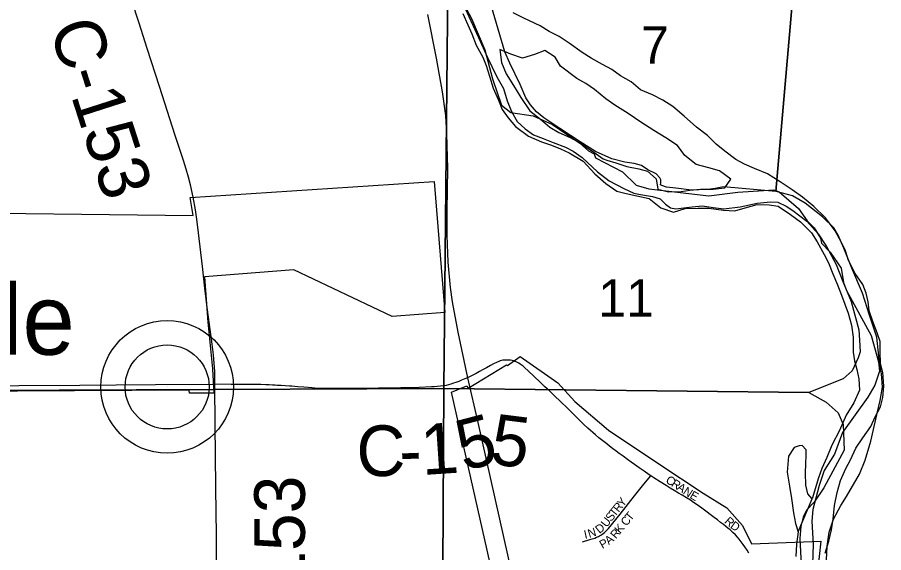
# Model space of a CAD drawing. Extents: x 0 to 680, y 0 to 440.
# Drawn here: x 499.3 to 516.42, y 256.23 to 266.81 of the extents above; entities that cross this region are included whole.
import ezdxf

# ---------------------------------------------------------------- set-up
doc = ezdxf.new("R2010")
doc.units = 0
for name, color, linetype in [('GM_X_City_Street', 7, 'Continuous'), ('GM_X_City_Street_Text', 7, 'Continuous'), ('GM_X_Corporation', 7, 'Continuous'), ('GM_X_County_Road', 7, 'Continuous'), ('GM_X_County_Road_Text', 7, 'Continuous'), ('GM_X_Major_River', 7, 'Continuous'), ('GM_X_Rail_Line', 7, 'Continuous'), ('GM_X_Section', 7, 'Continuous'), ('GM_X_Section_Text', 7, 'Continuous'), ('GM_X_Township', 7, 'Continuous'), ('GM_X_Township_Road', 7, 'Continuous'), ('GM_X_Unincorporated', 7, 'Continuous'), ('GM_X_Unincorporated_Location', 7, 'Continuous'), ('GM_X_Unincorporated_Text', 7, 'Continuous')]:
    doc.layers.add(name, color=color, linetype=linetype)

msp = doc.modelspace()

# ---------------------------------------------------------------- linework, layer by layer
at = {"layer": 'GM_X_City_Street'}
for points in [[(502.954, 261.886), (502.879, 262.549), (502.844, 262.821), (502.818, 263.005)], [(511.818, 257.749), (511.785, 257.77), (511.685, 257.837), (511.588, 257.905), (511.498, 257.969), (511.429, 258.019), (511.356, 258.073), (511.27, 258.135), (511.196, 258.189), (511.136, 258.232), (511.061, 258.289), (511.003, 258.334), (510.948, 258.377), (510.871, 258.437), (510.794, 258.499), (510.723, 258.558), (510.671, 258.603), (510.626, 258.642), (510.576, 258.689), (510.497, 258.764), (510.17, 259.084), (510.035, 259.213), (509.915, 259.328), (509.814, 259.426), (509.719, 259.516), (509.632, 259.597)], [(510.468, 256.444), (510.611, 256.487), (510.663, 256.502), (510.71, 256.518), (510.747, 256.532), (510.782, 256.548), (510.805, 256.561), (510.831, 256.576), (510.854, 256.591), (510.878, 256.608), (510.901, 256.627), (510.929, 256.652), (510.954, 256.678), (510.983, 256.709), (511.212, 256.99), (511.498, 257.353), (511.684, 257.583), (511.818, 257.749)], [(513.491, 256.58), (513.441, 256.629), (513.386, 256.678), (513.343, 256.714), (513.301, 256.747), (513.254, 256.784), (513.199, 256.827), (513.138, 256.875), (513.073, 256.926), (512.996, 256.982), (512.934, 257.03), (512.854, 257.089), (512.754, 257.16), (512.666, 257.223), (512.601, 257.265), (512.523, 257.312), (512.44, 257.363), (512.368, 257.406), (512.282, 257.457), (512.201, 257.506), (512.124, 257.553), (512.007, 257.627), (511.881, 257.708), (511.818, 257.749)], [(513.759, 256.217), (513.722, 256.28), (513.679, 256.343), (513.646, 256.393), (513.607, 256.445), (513.568, 256.493), (513.53, 256.536), (513.491, 256.58)]]:
    msp.add_lwpolyline(points, dxfattribs=at)
at = {"layer": 'GM_X_Corporation'}
for points in [[(497.251, 262.955), (502.772, 262.895), (502.714, 263.247), (507.536, 263.566), (507.745, 260.976), (506.707, 260.893), (504.759, 261.818), (502.993, 261.678), (503.065, 260.781), (503.151, 259.862), (503.178, 259.379), (502.698, 259.381), (502.694, 259.441), (498.159, 259.415)], [(509.824, 250.791), (507.877, 259.404), (508.185, 259.528), (508.21, 259.477), (508.965, 259.943), (508.986, 259.927), (509.235, 260.107), (509.983, 259.583), (510.317, 259.215), (510.982, 258.647), (511.979, 257.987), (512.857, 257.402), (513.32, 257.112), (513.634, 256.765), (513.808, 256.401), (515.179, 256.455), (515.114, 255.848)]]:
    msp.add_lwpolyline(points, dxfattribs=at)
at = {"layer": 'GM_X_County_Road'}
for points in [[(502.72, 263.496), (502.681, 263.647), (502.634, 263.811), (502.579, 263.982), (502.419, 264.471), (502.108, 265.44), (501.864, 266.19), (501.705, 266.691), (501.555, 267.16)], [(502.818, 263.005), (502.772, 263.255), (502.72, 263.496)], [(503.2, 259.686), (503.197, 259.817), (503.187, 259.967), (503.171, 260.14), (503.147, 260.348), (503.116, 260.592), (503.051, 261.073), (503.002, 261.457), (502.954, 261.886)], [(509.632, 259.597), (509.393, 259.822), (509.328, 259.883), (509.293, 259.912), (509.258, 259.938), (509.236, 259.954), (509.21, 259.972), (509.184, 259.986), (509.158, 259.998), (509.132, 260.009), (509.106, 260.018), (509.076, 260.025), (509.048, 260.03), (509.015, 260.033), (508.984, 260.034), (508.957, 260.034), (508.923, 260.033), (508.894, 260.03), (508.868, 260.025), (508.844, 260.02), (508.813, 260.009), (508.767, 259.989), (508.712, 259.962), (508.647, 259.925), (508.574, 259.883), (508.508, 259.847), (508.435, 259.808), (508.369, 259.772), (508.311, 259.741), (508.248, 259.711), (508.193, 259.686), (508.143, 259.665), (508.074, 259.636), (508.021, 259.614), (507.963, 259.592), (507.921, 259.576), (507.867, 259.557), (507.818, 259.543), (507.773, 259.533), (507.72, 259.524), (507.662, 259.517), (507.596, 259.511), (507.534, 259.507), (507.482, 259.504), (507.241, 259.495), (506.875, 259.485), (505.991, 259.476), (505.336, 259.473), (505.249, 259.476), (505.178, 259.481), (505.118, 259.485), (505.047, 259.491), (504.958, 259.498), (504.842, 259.507), (504.722, 259.517), (504.674, 259.521), (504.59, 259.527), (504.511, 259.531), (504.435, 259.535), (504.391, 259.537), (504.34, 259.54), (504.273, 259.543), (504.208, 259.547), (504.112, 259.549), (503.968, 259.551), (503.761, 259.552), (503.521, 259.554), (503.203, 259.558)], [(503.203, 259.558), (503.2, 259.686)], [(503.244, 254.088), (503.236, 255.241), (503.234, 256.578), (503.218, 257.499), (503.213, 258.176), (503.21, 258.735), (503.203, 259.558)]]:
    msp.add_lwpolyline(points, dxfattribs=at)
at = {"layer": 'GM_X_Major_River'}
msp.add_line((514.732, 256.638), (515.007, 257.29), dxfattribs=at)
for points in [[(508.102, 266.885), (508.199, 266.663), (508.284, 266.481), (508.368, 266.26), (508.499, 266.024), (508.564, 265.856), (508.629, 265.648), (508.706, 265.406), (508.81, 265.171), (508.881, 264.989), (509, 264.821), (509.145, 264.652), (509.403, 264.461), (509.656, 264.351), (509.856, 264.282), (510.035, 264.212), (510.208, 264.13), (510.48, 263.966), (510.711, 263.716), (510.929, 263.526), (511.148, 263.376), (511.335, 263.327), (511.541, 263.278), (511.788, 263.228), (512.02, 263.044), (512.266, 262.961), (512.501, 263.032), (512.748, 263.035), (512.969, 263.039), (513.256, 262.996), (513.483, 262.986), (513.684, 263.044), (513.919, 263.108), (514.159, 263.105), (514.339, 263.076), (514.578, 262.913), (514.777, 262.77), (514.995, 262.553), (515.106, 262.371), (515.244, 262.122), (515.335, 261.954), (515.42, 261.739), (515.511, 261.524), (515.589, 261.315), (515.653, 261.141), (515.718, 260.959), (515.789, 260.725), (515.819, 260.49), (515.823, 260.189), (515.847, 260.022), (515.892, 259.847), (515.93, 259.666), (515.948, 259.439), (515.831, 259.193), (515.681, 258.947), (515.55, 258.641), (515.4, 258.355), (515.297, 258.109), (515.201, 257.89), (515.132, 257.71), (515.007, 257.29)], [(514.816, 263.257), (514.611, 263.4), (514.378, 263.557), (514.126, 263.714), (513.867, 263.824), (513.674, 263.907), (513.501, 263.996), (513.283, 264.166), (513.111, 264.301), (512.939, 264.471), (512.72, 264.641), (512.482, 264.858), (512.257, 265.048), (512.058, 265.17), (511.852, 265.28), (511.613, 265.376), (511.428, 265.533), (511.222, 265.655), (511.049, 265.778), (510.863, 265.874), (510.638, 266.004), (510.459, 266.113), (510.207, 266.297), (510.008, 266.433), (509.808, 266.529), (509.629, 266.638), (509.31, 266.789), (509.098, 266.899)], [(510.034, 265.844), (509.929, 266.019), (509.724, 266.156), (509.522, 266.071), (509.281, 266.001), (509.055, 266.084), (508.835, 266.173), (508.866, 265.919), (508.957, 265.69), (509.108, 265.461), (509.252, 265.225), (509.429, 264.962), (509.641, 264.793), (509.82, 264.636), (509.999, 264.534), (510.225, 264.437), (510.418, 264.328), (510.65, 264.178), (510.875, 264.015)], [(510.875, 264.015), (510.948, 263.987), (511.128, 263.931), (511.348, 263.862), (511.581, 263.812), (511.754, 263.77), (511.926, 263.614), (511.957, 263.413), (512.171, 263.363), (512.418, 263.367), (512.592, 263.392), (512.8, 263.416), (513.053, 263.413), (513.281, 263.437), (513.403, 263.609), (513.178, 263.772), (512.965, 263.835), (512.718, 263.898), (512.493, 264.075), (512.348, 264.277), (512.116, 264.427), (511.877, 264.571), (511.619, 264.734), (511.373, 264.911), (511.108, 265.075), (510.929, 265.198), (510.704, 265.381), (510.532, 265.504), (510.359, 265.599), (510.034, 265.844)], [(515.268, 256.217), (515.338, 256.457), (515.394, 256.677), (515.423, 256.891), (515.453, 257.158), (515.503, 257.418), (515.572, 257.658), (515.675, 257.891), (515.764, 258.063), (515.874, 258.296), (516.01, 258.495), (516.166, 258.721), (516.255, 258.913), (516.358, 259.113), (516.407, 259.293), (516.423, 259.52), (516.406, 259.788), (516.361, 259.975), (516.351, 260.196), (516.353, 260.403), (516.295, 260.571), (516.211, 260.8), (516.133, 261.008), (516.115, 261.189), (516.077, 261.356), (516.012, 261.531), (515.861, 261.747), (515.73, 262.003), (515.666, 262.191), (515.587, 262.359), (515.463, 262.588), (515.272, 262.844), (515.041, 263.067), (514.816, 263.257)], [(515.007, 257.29), (514.921, 257.392), (514.883, 257.566), (514.879, 257.8), (514.881, 257.994), (514.89, 258.148), (514.891, 258.261), (514.812, 258.349), (514.752, 258.343), (514.651, 258.304), (514.542, 258.139), (514.512, 257.818), (514.562, 257.543), (514.599, 257.302), (514.642, 257.014), (514.68, 256.806), (514.732, 256.638)], [(514.732, 256.638), (514.702, 256.398), (514.686, 256.151)]]:
    msp.add_lwpolyline(points, dxfattribs=at)
at = {"layer": 'GM_X_Rail_Line'}
msp.add_lwpolyline([(509.833, 252.424), (508.403, 258.802), (508.204, 259.684), (508.01, 260.587), (507.897, 261.189), (507.862, 261.469), (507.813, 261.97), (507.796, 262.499), (507.796, 262.991), (507.804, 263.821), (507.787, 264.503), (507.764, 264.868), (507.703, 265.339), (507.582, 265.999), (507.408, 266.867)], dxfattribs=at)
at = {"layer": 'GM_X_Section'}
for points in [[(514.746, 268.599), (514.294, 263.368), (513.255, 263.461), (513.094, 263.424), (512.953, 263.406), (512.766, 263.397), (512.626, 263.392), (512.313, 263.432), (512.127, 263.449), (512.04, 263.484), (512.014, 263.497), (512.015, 263.537), (512.016, 263.597), (511.997, 263.638), (511.925, 263.713), (511.759, 263.796), (511.634, 263.878), (511.488, 263.921), (511.308, 263.944), (511.049, 264.009), (510.725, 264.156), (510.421, 264.348), (510.019, 264.609), (509.703, 264.822), (509.558, 264.938), (509.441, 265.081), (509.35, 265.216), (509.234, 265.478), (509.035, 265.903), (508.933, 266.125), (508.638, 267.138)], [(515.293, 256.087), (515.304, 256.354), (515.343, 256.633), (515.434, 256.892), (515.573, 257.163), (515.69, 257.341), (515.945, 257.777), (516.057, 258.055), (516.171, 258.434), (516.222, 258.66), (516.302, 259.012), (516.353, 259.238), (516.398, 259.497), (516.383, 259.764), (516.34, 259.999), (516.329, 260.113), (516.289, 260.487), (516.144, 260.924), (516.006, 261.36), (515.794, 261.851), (515.635, 262.248), (515.526, 262.504), (515.436, 262.646), (515.213, 262.863), (514.871, 263.137), (514.62, 263.282), (514.42, 263.332), (514.294, 263.368), (514.746, 268.599)], [(507.809, 267.427), (507.727, 259.473), (489.476, 259.394)], [(508.148, 266.981), (508.411, 266.408), (508.59, 266.018), (508.777, 265.634), (508.906, 265.405), (508.981, 265.156), (509.064, 264.948), (509.174, 264.752), (509.338, 264.602), (509.503, 264.486), (509.688, 264.415), (509.887, 264.332), (510.132, 264.24), (510.284, 264.164), (510.462, 264.04), (510.764, 263.754), (510.994, 263.577), (511.285, 263.424), (511.484, 263.334), (511.617, 263.305), (511.856, 263.267), (512.002, 263.224), (512.107, 263.115), (512.206, 263.047), (512.312, 263.025), (512.473, 263.042), (512.64, 263.065), (512.841, 263.081), (513.054, 263.051), (513.26, 263.027), (513.588, 263.061), (513.923, 263.135), (514.184, 263.163), (514.33, 263.154), (514.496, 263.077), (514.628, 262.988), (514.904, 262.782), (515.126, 262.531), (515.295, 262.281), (515.482, 261.924), (515.616, 261.588), (515.782, 261.191), (515.932, 260.634), (515.948, 260.427), (515.957, 260.2), (515.921, 260.08), (515.803, 259.822), (515.62, 259.665), (514.941, 259.391), (507.727, 259.473), (507.809, 267.427)], [(507.628, 241.733), (507.727, 259.473), (514.941, 259.391), (515.284, 259.204), (515.521, 258.993), (515.623, 258.764), (515.64, 258.257), (515.239, 257.51), (515.047, 257.226), (514.897, 257.069), (514.834, 256.93), (514.784, 256.744), (514.767, 256.511), (514.801, 255.856)]]:
    msp.add_lwpolyline(points, dxfattribs=at)
msp.add_lwpolyline([(507.727, 259.473), (507.628, 241.733), (499.118, 242.119), (489.987, 242.13), (489.813, 253.134), (489.476, 259.394)], close=True, dxfattribs=at)
at = {"layer": 'GM_X_Township'}
msp.add_lwpolyline([(507.988, 267.317), (508.275, 266.784), (508.541, 266.165), (508.688, 265.594), (508.868, 265.076), (509.053, 264.926), (509.494, 264.86), (509.873, 264.694), (510.417, 264.325), (510.589, 264.168), (510.702, 264.113), (510.728, 264.032), (511.26, 263.757), (511.531, 263.492), (511.777, 263.422), (512.967, 263.278), (513.537, 263.351), (514.254, 263.401), (514.36, 263.359), (514.737, 263.033), (514.908, 262.79), (515.047, 262.647), (515.171, 262.445), (515.196, 262.344), (515.368, 262.168), (515.585, 261.85), (515.628, 261.568), (515.686, 261.407), (516.176, 260.523), (516.323, 259.999), (516.34, 259.818), (516.249, 259.539), (516.112, 259.3), (515.607, 258.604), (515.448, 258.178), (515.249, 257.852), (515.145, 257.559), (515.024, 257.079), (515.001, 256.852), (515.028, 256.39), (515.004, 255.607)], dxfattribs=at)
msp.add_lwpolyline([(507.988, 267.317), (508.275, 266.784), (508.541, 266.165), (508.688, 265.594), (508.868, 265.076), (509.053, 264.926), (509.494, 264.86), (509.873, 264.694), (510.417, 264.325), (510.589, 264.168), (510.702, 264.113), (510.728, 264.032), (511.26, 263.757), (511.531, 263.492), (511.777, 263.422), (512.967, 263.278), (513.537, 263.351), (514.254, 263.401), (514.36, 263.359), (514.737, 263.033), (514.908, 262.79), (515.047, 262.647), (515.171, 262.445), (515.196, 262.344), (515.368, 262.168), (515.585, 261.85), (515.628, 261.568), (515.686, 261.407), (516.176, 260.523), (516.323, 259.999), (516.34, 259.818), (516.249, 259.539), (516.112, 259.3), (515.607, 258.604), (515.448, 258.178), (515.249, 257.852), (515.145, 257.559), (515.024, 257.079), (515.001, 256.852), (515.028, 256.39), (515.004, 255.607)], dxfattribs=at)
at = {"layer": 'GM_X_Township_Road'}
msp.add_lwpolyline([(498.606, 259.527), (499.325, 259.531), (500.528, 259.539), (501.248, 259.544), (502.026, 259.55), (503.203, 259.558)], dxfattribs=at)
at = {"layer": 'GM_X_Unincorporated'}
for radius in [1.311, 0.831]:
    msp.add_circle((502.258, 259.505), radius, dxfattribs=at)
at = {"layer": 'GM_X_Unincorporated_Location'}
msp.add_line((502.258, 259.505), (502.258, 259.505), dxfattribs=at)

# ---------------------------------------------------------------- texts
at = {"layer": 'GM_X_City_Street_Text'}
for s, rotation, p in [('C', 326.8825, (512.098, 257.626)), ('R', 326.8621, (512.209, 257.554)), ('A', 326.8591, (512.32, 257.482)), ('N', 326.8746, (512.443, 257.401)), ('E', 330.2103, (512.575, 257.316)), ('Y', 51.1627, (511.267, 257.118)), ('T', 51.1738, (511.11, 256.924)), ('R', 51.1771, (511.184, 257.015)), ('U', 51.6681, (510.946, 256.717)), ('S', 51.1738, (511.037, 256.832)), ('C', 50.4867, (511.336, 256.741)), ('T', 50.5393, (511.421, 256.843)), ('R', 318.2818, (513.262, 256.83)), ('D', 39.0247, (510.804, 256.596)), ('K', 50.3667, (511.214, 256.594)), ('D', 324.8235, (513.377, 256.729)), ('I', 12.8701, (510.518, 256.5)), ('N', 17.4728, (510.603, 256.52)), ('R', 50.0953, (511.129, 256.492)), ('P', 28.9484, (510.861, 256.3)), ('A', 39.0088, (510.99, 256.375))]:
    msp.add_text(s, height=0.167, rotation=rotation, dxfattribs=at).set_placement(p)
at = {"layer": 'GM_X_County_Road_Text'}
for s, height, rotation, p in [('C-153', 1.0014, 287.8286, (499.92, 266.61)), ('5', 1.001, 14.5863, (508.121, 257.836)), ('5', 1.001, 352.9253, (508.619, 257.985)), ('C', 1.001, 0.2849, (506.002, 257.74)), ('1', 1.001, 3.8421, (507.303, 257.762)), ('-', 1.001, 2.147, (506.86, 257.745)), ('C-153', 1.0014, 90, (504.98, 254.104))]:
    msp.add_text(s, height=height, rotation=rotation, dxfattribs=at).set_placement(p)
at = {"layer": 'GM_X_Section_Text'}
for s, height, p in [('7', 0.738, (511.626, 265.893)), ('11', 0.7377, (510.781, 260.891))]:
    msp.add_text(s, height=height, rotation=0, dxfattribs=at).set_placement(p)
at = {"layer": 'GM_X_Unincorporated_Text'}
msp.add_text('Cowlesville', height=1.39189, rotation=0, dxfattribs=at).set_placement((491.123, 260.14))

doc.saveas('drawing.dxf')
